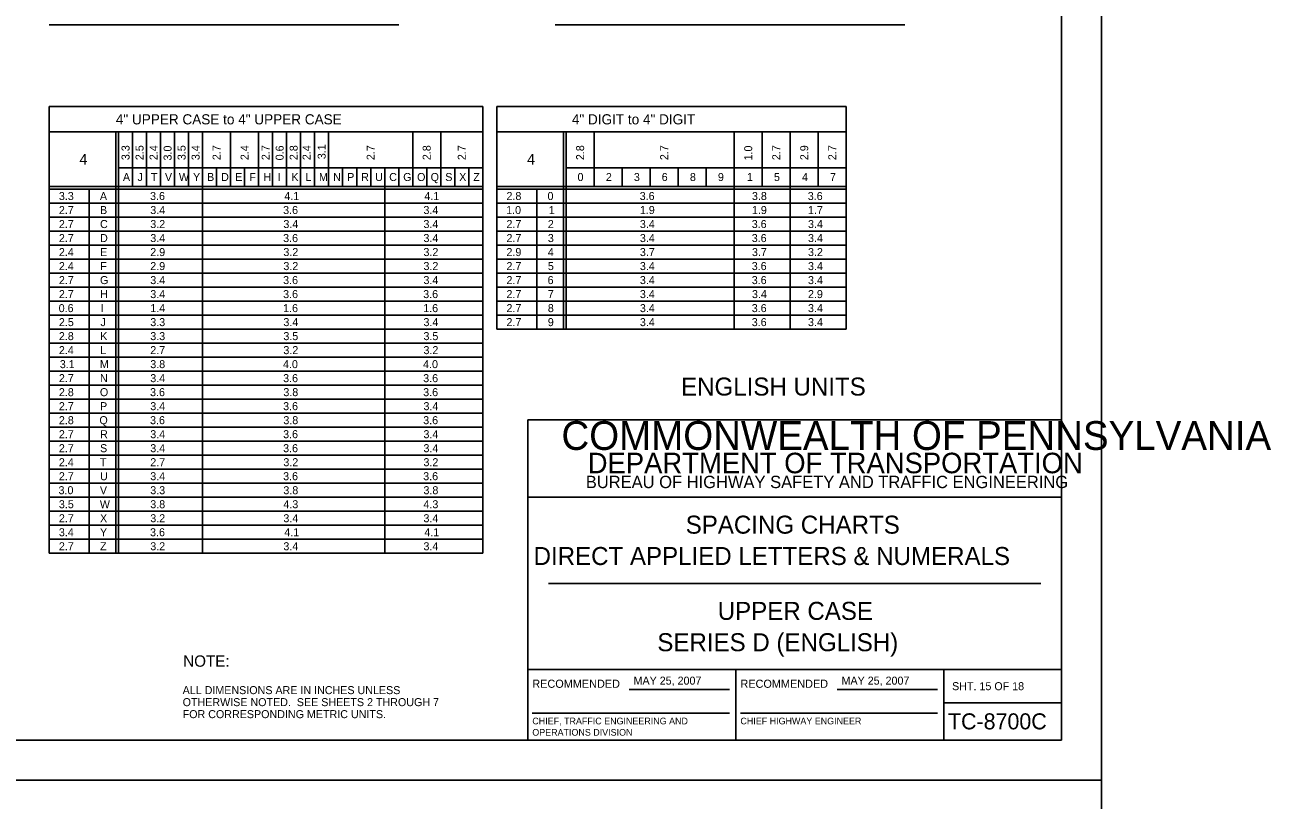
# Model space of a CAD drawing. Extents: x 637580 to 641849, y 297270 to 299646.
# Drawn here: x 640540.8 to 641007.9, y 297856.1 to 298146.6 of the extents above; entities that cross this region are included whole.
import ezdxf

# ---------------------------------------------------------------- set-up
doc = ezdxf.new("R2010")
doc.units = 0
for name, color, linetype in [('1', 7, 'Continuous'), ('2', 7, 'Continuous'), ('XCS-GRID-HVGL', 7, 'Continuous')]:
    doc.layers.add(name, color=color, linetype=linetype)

msp = doc.modelspace()

# ---------------------------------------------------------------- linework, layer by layer
at = {"layer": '1'}
for p, q in [((640929.31, 297878.63), (640929.31, 298442.63)), ((640729.31, 297878.63), (640729.31, 297998.63)), ((640729.31, 297998.63), (640929.31, 297998.63)), ((640929.31, 297969.63), (640729.31, 297969.63)), ((640737.06, 297937.31), (640921.56, 297937.31)), ((640729.31, 297905), (640929.31, 297905)), ((640807.31, 297905), (640807.31, 297878.63)), ((640885.19, 297878.63), (640885.19, 297905)), ((640767.24, 297897.57), (640804.87, 297897.57)), ((640845.24, 297897.57), (640882.87, 297897.57)), ((640730.99, 297888.68), (640804.87, 297888.68)), ((640808.99, 297888.68), (640882.87, 297888.68)), ((640885.19, 297892.63), (640929.31, 297892.63)), ((640929.31, 297878.63), (640143.31, 297878.63)), ((640143.31, 297878.63), (640729.31, 297878.63))]:
    msp.add_line(p, q, dxfattribs=at)
at = {"layer": '2'}
for p, q in [((640549.91, 298146.63), (640680.91, 298146.63)), ((640739.61, 298146.63), (640870.61, 298146.63)), ((640712.41, 298116), (640549.91, 298116)), ((640549.91, 298116), (640549.91, 297948.63)), ((640712.41, 298116), (640712.41, 297948.63)), ((640848.66, 298116), (640717.66, 298116)), ((640717.66, 298116), (640717.66, 298032.63)), ((640848.66, 298032.63), (640848.66, 298116)), ((640549.91, 298106.5), (640712.41, 298106.5)), ((640574.91, 298106.5), (640574.91, 297948.63)), ((640575.91, 298106.5), (640575.91, 297948.63)), ((640581.16, 298106.5), (640581.16, 298086.13)), ((640586.41, 298106.5), (640586.41, 298086.13)), ((640591.66, 298106.5), (640591.66, 298086.13)), ((640596.91, 298106.5), (640596.91, 298086.13)), ((640602.16, 298106.5), (640602.16, 298086.13)), ((640607.41, 298106.5), (640607.41, 297948.63)), ((640617.91, 298106.5), (640617.91, 298086.13)), ((640628.41, 298106.5), (640628.41, 298086.13)), ((640633.66, 298106.5), (640633.66, 298086.13)), ((640638.91, 298106.5), (640638.91, 298086.13)), ((640644.16, 298106.5), (640644.16, 298086.13)), ((640649.41, 298106.5), (640649.41, 298086.13)), ((640654.66, 298106.5), (640654.66, 298086.13)), ((640686.16, 298106.5), (640686.16, 298086.13)), ((640696.66, 298106.5), (640696.66, 298086.13)), ((640717.66, 298106.5), (640848.66, 298106.5)), ((640742.66, 298106.5), (640742.66, 298032.63)), ((640743.66, 298106.5), (640743.66, 298032.63)), ((640754.16, 298106.5), (640754.16, 298086.13)), ((640806.66, 298106.5), (640806.66, 298032.63)), ((640817.16, 298106.5), (640817.16, 298086.13)), ((640827.66, 298106.5), (640827.66, 298032.63)), ((640838.16, 298106.5), (640838.16, 298086.13)), ((640575.91, 298093.13), (640712.41, 298093.13)), ((640612.66, 298093.13), (640612.66, 298086.13)), ((640623.16, 298093.13), (640623.16, 298086.13)), ((640659.91, 298093.13), (640659.91, 298086.13)), ((640665.16, 298093.13), (640665.16, 298086.13)), ((640670.41, 298093.13), (640670.41, 298086.13)), ((640670.41, 298093.13), (640670.41, 298086.13)), ((640675.66, 298093.13), (640675.66, 297948.63)), ((640680.91, 298093.13), (640680.91, 298086.13)), ((640691.41, 298093.13), (640691.41, 298086.13)), ((640701.91, 298093.13), (640701.91, 298086.13)), ((640707.16, 298093.13), (640707.16, 298086.13)), ((640743.66, 298093.13), (640848.66, 298093.13)), ((640764.66, 298093.13), (640764.66, 298086.13)), ((640775.16, 298093.13), (640775.16, 298086.13)), ((640785.66, 298093.13), (640785.66, 298086.13)), ((640796.16, 298093.13), (640796.16, 298086.13)), ((640712.41, 298086.13), (640549.91, 298086.13)), ((640712.41, 298085.13), (640549.91, 298085.13)), ((640564.91, 298085.13), (640564.91, 297948.63)), ((640848.66, 298086.13), (640717.66, 298086.13)), ((640848.66, 298085.13), (640717.66, 298085.13)), ((640732.66, 298085.13), (640732.66, 298032.63)), ((640712.41, 298079.88), (640549.91, 298079.88)), ((640848.66, 298079.88), (640717.66, 298079.88)), ((640712.41, 298074.63), (640549.91, 298074.63)), ((640848.66, 298074.63), (640717.66, 298074.63)), ((640712.41, 298069.38), (640549.91, 298069.38)), ((640848.66, 298069.38), (640717.66, 298069.38)), ((640712.41, 298064.13), (640549.91, 298064.13)), ((640848.66, 298064.13), (640717.66, 298064.13)), ((640712.41, 298058.88), (640549.91, 298058.88)), ((640848.66, 298058.88), (640717.66, 298058.88)), ((640712.41, 298053.63), (640549.91, 298053.63)), ((640848.66, 298053.63), (640717.66, 298053.63)), ((640712.41, 298048.38), (640549.91, 298048.38)), ((640848.66, 298048.38), (640717.66, 298048.38)), ((640712.41, 298043.13), (640549.91, 298043.13)), ((640848.66, 298043.13), (640717.66, 298043.13)), ((640712.41, 298037.88), (640549.91, 298037.88)), ((640848.66, 298037.88), (640717.66, 298037.88)), ((640712.41, 298032.63), (640549.91, 298032.63)), ((640717.66, 298032.63), (640848.66, 298032.63)), ((640712.41, 298027.38), (640549.91, 298027.38)), ((640712.41, 298022.13), (640549.91, 298022.13)), ((640712.41, 298016.88), (640549.91, 298016.88)), ((640712.41, 298011.63), (640549.91, 298011.63)), ((640712.41, 298006.38), (640549.91, 298006.38)), ((640712.41, 298001.13), (640549.91, 298001.13)), ((640712.41, 297995.88), (640549.91, 297995.88)), ((640712.41, 297990.63), (640549.91, 297990.63)), ((640712.41, 297985.38), (640549.91, 297985.38)), ((640712.41, 297980.13), (640549.91, 297980.13)), ((640712.41, 297974.88), (640549.91, 297974.88)), ((640712.41, 297969.63), (640549.91, 297969.63)), ((640712.41, 297964.38), (640549.91, 297964.38)), ((640712.41, 297959.13), (640549.91, 297959.13)), ((640712.41, 297953.88), (640549.91, 297953.88)), ((640549.91, 297948.63), (640549.91, 297948.63)), ((640549.91, 297948.63), (640712.41, 297948.63))]:
    msp.add_line(p, q, dxfattribs=at)
at = {"layer": 'XCS-GRID-HVGL'}
for points in [[(640103.31, 298457.63), (640944.31, 298457.63), (640944.31, 297863.63), (640103.31, 297863.63)], [(640103.31, 297863.63), (640944.31, 297863.63), (640944.31, 297269.63), (640103.31, 297269.63)]]:
    msp.add_lwpolyline(points, close=True, dxfattribs=at)

# ---------------------------------------------------------------- texts
at = {"layer": '1'}
for s, height, p in [('COMMONWEALTH OF PENNSYLVANIA', 10.7828, (640741.9, 297987.36)), ('DEPARTMENT OF TRANSPORTATION', 7.6837, (640751.76, 297978.61)), ('BUREAU OF HIGHWAY SAFETY AND TRAFFIC ENGINEERING', 4.6253, (640751.04, 297973.04)), ('SPACING CHARTS', 6.75, (640788.47, 297955.97)), ('DIRECT APPLIED LETTERS & NUMERALS', 6.75, (640731.47, 297944.22)), ('UPPER CASE', 6.75, (640800.47, 297923.66)), ('SERIES D (ENGLISH)', 6.75, (640777.84, 297911.91)), ('RECOMMENDED', 3.048, (640730.99, 297898.2)), ('RECOMMENDED', 3.048, (640808.99, 297898.2)), ('SHT. 15 OF 18', 3, (640888.32, 297897.31)), ('TC-8700C', 6, (640886.77, 297882.63)), ('CHIEF, TRAFFIC ENGINEERING AND', 2.5, (640730.99, 297884.51)), ('CHIEF HIGHWAY ENGINEER', 2.5, (640808.99, 297884.51)), ('OPERATIONS DIVISION', 2.5, (640730.99, 297880.26))]:
    msp.add_text(s, height=height, dxfattribs=at).set_placement(p)
at = {"layer": '2'}
for s, height, p in [('4" UPPER CASE to 4" UPPER CASE', 3.8, (640574.9, 298109.35)), ('4" DIGIT to 4" DIGIT', 3.8, (640745.81, 298109.35)), ('4', 4, (640561.28, 298094.31)), ('4', 4, (640729.03, 298094.31)), ('A', 3, (640577.56, 298088.13)), ('J', 3, (640583.04, 298088.13)), ('T', 3, (640588.04, 298088.13)), ('V', 3, (640593.31, 298088.13)), ('W', 3, (640598.53, 298088.13)), ('Y', 3, (640603.84, 298088.13)), ('B', 3, (640609.1, 298088.13)), ('D', 3, (640614.35, 298088.13)), ('E', 3, (640619.62, 298088.13)), ('F', 3, (640624.92, 298088.13)), ('H', 3, (640630.19, 298088.13)), ('I', 3, (640635.6, 298088.13)), ('K', 3, (640640.69, 298088.13)), ('L', 3, (640645.94, 298088.13)), ('M', 3, (640651.03, 298088.13)), ('N', 3, (640656.35, 298088.13)), ('P', 3, (640661.6, 298088.13)), ('R', 3, (640666.85, 298088.13)), ('U', 3, (640672.09, 298088.13)), ('C', 3, (640677.35, 298088.13)), ('G', 3, (640682.6, 298088.13)), ('O', 3, (640687.81, 298088.13)), ('Q', 3, (640692.88, 298088.13)), ('S', 3, (640698.37, 298088.13)), ('X', 3, (640703.59, 298088.13)), ('Z', 3, (640708.85, 298088.13)), ('0', 3, (640747.93, 298088.13)), ('2', 3, (640758.56, 298088.13)), ('3', 3, (640769.06, 298088.13)), ('6', 3, (640779.48, 298088.13)), ('8', 3, (640790.06, 298088.13)), ('9', 3, (640800.55, 298088.13)), ('1', 3, (640811.4, 298088.13)), ('5', 3, (640821.56, 298088.13)), ('4', 3, (640832.06, 298088.13)), ('7', 3, (640842.56, 298088.13)), ('3.3', 3, (640553.56, 298081)), ('A', 3, (640568.93, 298081)), ('3.6', 3, (640587.73, 298081)), ('4.1', 3, (640638.03, 298081)), ('4.1', 3, (640690.53, 298081)), ('2.8', 3, (640721.31, 298081)), ('0', 3, (640736.68, 298081)), ('3.6', 3, (640771.23, 298081)), ('3.8', 3, (640813.31, 298081)), ('3.6', 3, (640834.23, 298081)), ('2.7', 3, (640553.56, 298075.75)), ('B', 3, (640568.98, 298075.75)), ('3.4', 3, (640587.81, 298075.75)), ('3.6', 3, (640637.6, 298075.75)), ('3.4', 3, (640690.19, 298075.75)), ('1.0', 3, (640721.18, 298075.75)), ('1', 3, (640737.15, 298075.75)), ('1.9', 3, (640771.3, 298075.75)), ('1.9', 3, (640813.3, 298075.75)), ('1.7', 3, (640834.31, 298075.75)), ('2.7', 3, (640553.56, 298070.5)), ('C', 3, (640568.98, 298070.5)), ('3.2', 3, (640587.81, 298070.5)), ('3.4', 3, (640637.69, 298070.5)), ('3.4', 3, (640690.19, 298070.5)), ('2.7', 3, (640721.31, 298070.5)), ('2', 3, (640736.81, 298070.5)), ('3.4', 3, (640771.31, 298070.5)), ('3.6', 3, (640813.23, 298070.5)), ('3.4', 3, (640834.31, 298070.5)), ('2.7', 3, (640553.56, 298065.25)), ('D', 3, (640568.98, 298065.25)), ('3.4', 3, (640587.81, 298065.25)), ('3.6', 3, (640637.6, 298065.25)), ('3.4', 3, (640690.19, 298065.25)), ('2.7', 3, (640721.31, 298065.25)), ('3', 3, (640736.81, 298065.25)), ('3.4', 3, (640771.31, 298065.25)), ('3.6', 3, (640813.23, 298065.25)), ('3.4', 3, (640834.31, 298065.25)), ('2.4', 3, (640553.56, 298060)), ('E', 3, (640568.99, 298060)), ('2.9', 3, (640587.8, 298060)), ('3.2', 3, (640637.69, 298060)), ('3.2', 3, (640690.19, 298060)), ('2.9', 3, (640721.3, 298060)), ('4', 3, (640736.81, 298060)), ('3.7', 3, (640771.31, 298060)), ('3.7', 3, (640813.31, 298060)), ('3.2', 3, (640834.31, 298060)), ('2.4', 3, (640553.56, 298054.75)), ('F', 3, (640569.05, 298054.75)), ('2.9', 3, (640587.8, 298054.75)), ('3.2', 3, (640637.69, 298054.75)), ('3.2', 3, (640690.19, 298054.75)), ('2.7', 3, (640721.31, 298054.75)), ('5', 3, (640736.81, 298054.75)), ('3.4', 3, (640771.31, 298054.75)), ('3.6', 3, (640813.23, 298054.75)), ('3.4', 3, (640834.31, 298054.75)), ('2.7', 3, (640553.56, 298049.5)), ('G', 3, (640568.98, 298049.5)), ('3.4', 3, (640587.81, 298049.5)), ('3.6', 3, (640637.6, 298049.5)), ('3.4', 3, (640690.19, 298049.5)), ('2.7', 3, (640721.31, 298049.5)), ('6', 3, (640736.73, 298049.5)), ('3.4', 3, (640771.31, 298049.5)), ('3.6', 3, (640813.23, 298049.5)), ('3.4', 3, (640834.31, 298049.5)), ('2.7', 3, (640553.56, 298044.25)), ('H', 3, (640569.06, 298044.25)), ('3.4', 3, (640587.81, 298044.25)), ('3.6', 3, (640637.6, 298044.25)), ('3.6', 3, (640690.1, 298044.25)), ('2.7', 3, (640721.31, 298044.25)), ('7', 3, (640736.81, 298044.25)), ('3.4', 3, (640771.31, 298044.25)), ('3.4', 3, (640813.31, 298044.25)), ('2.9', 3, (640834.3, 298044.25)), ('0.6', 3, (640553.48, 298039)), ('I', 3, (640569.23, 298039)), ('1.4', 3, (640587.81, 298039)), ('1.6', 3, (640637.6, 298039)), ('1.6', 3, (640690.1, 298039)), ('2.7', 3, (640721.31, 298039)), ('8', 3, (640736.81, 298039)), ('3.4', 3, (640771.31, 298039)), ('3.6', 3, (640813.23, 298039)), ('3.4', 3, (640834.31, 298039)), ('2.5', 3, (640553.56, 298033.75)), ('J', 3, (640569.17, 298033.75)), ('3.3', 3, (640587.81, 298033.75)), ('3.4', 3, (640637.69, 298033.75)), ('3.4', 3, (640690.19, 298033.75)), ('2.7', 3, (640721.31, 298033.75)), ('9', 3, (640736.8, 298033.75)), ('3.4', 3, (640771.31, 298033.75)), ('3.6', 3, (640813.23, 298033.75)), ('3.4', 3, (640834.31, 298033.75)), ('2.8', 3, (640553.56, 298028.5)), ('K', 3, (640569.06, 298028.5)), ('3.3', 3, (640587.81, 298028.5)), ('3.5', 3, (640637.69, 298028.5)), ('3.5', 3, (640690.19, 298028.5)), ('2.4', 3, (640553.56, 298023.25)), ('L', 3, (640569.06, 298023.25)), ('2.7', 3, (640587.81, 298023.25)), ('3.2', 3, (640637.69, 298023.25)), ('3.2', 3, (640690.19, 298023.25)), ('3.1', 3, (640553.9, 298018)), ('M', 3, (640568.91, 298018)), ('3.8', 3, (640587.81, 298018)), ('4.0', 3, (640637.56, 298018)), ('4.0', 3, (640690.06, 298018)), ('2.7', 3, (640553.56, 298012.75)), ('N', 3, (640568.98, 298012.75)), ('3.4', 3, (640587.81, 298012.75)), ('3.6', 3, (640637.6, 298012.75)), ('3.6', 3, (640690.1, 298012.75)), ('ENGLISH UNITS', 6.75, (640786.74, 298007.72)), ('2.8', 3, (640553.56, 298007.5)), ('O', 3, (640568.93, 298007.5)), ('3.6', 3, (640587.73, 298007.5)), ('3.8', 3, (640637.69, 298007.5)), ('3.6', 3, (640690.1, 298007.5)), ('2.7', 3, (640553.56, 298002.25)), ('P', 3, (640568.98, 298002.25)), ('3.4', 3, (640587.81, 298002.25)), ('3.6', 3, (640637.6, 298002.25)), ('3.4', 3, (640690.19, 298002.25)), ('2.8', 3, (640553.56, 297997)), ('Q', 3, (640568.75, 297997)), ('3.6', 3, (640587.73, 297997)), ('3.8', 3, (640637.69, 297997)), ('3.6', 3, (640690.1, 297997)), ('2.7', 3, (640553.56, 297991.75)), ('R', 3, (640568.98, 297991.75)), ('3.4', 3, (640587.81, 297991.75)), ('3.6', 3, (640637.6, 297991.75)), ('3.4', 3, (640690.19, 297991.75)), ('2.7', 3, (640553.56, 297986.5)), ('S', 3, (640568.99, 297986.5)), ('3.4', 3, (640587.81, 297986.5)), ('3.6', 3, (640637.6, 297986.5)), ('3.4', 3, (640690.19, 297986.5)), ('2.4', 3, (640553.56, 297981.25)), ('T', 3, (640568.92, 297981.25)), ('2.7', 3, (640587.81, 297981.25)), ('3.2', 3, (640637.69, 297981.25)), ('3.2', 3, (640690.19, 297981.25)), ('2.7', 3, (640553.56, 297976)), ('U', 3, (640568.97, 297976)), ('3.4', 3, (640587.81, 297976)), ('3.6', 3, (640637.6, 297976)), ('3.6', 3, (640690.1, 297976)), ('3.0', 3, (640553.43, 297970.75)), ('V', 3, (640568.93, 297970.75)), ('3.3', 3, (640587.81, 297970.75)), ('3.8', 3, (640637.69, 297970.75)), ('3.8', 3, (640690.19, 297970.75)), ('3.5', 3, (640553.56, 297965.5)), ('W', 3, (640568.91, 297965.5)), ('3.8', 3, (640587.81, 297965.5)), ('4.3', 3, (640637.69, 297965.5)), ('4.3', 3, (640690.19, 297965.5)), ('2.7', 3, (640553.56, 297960.25)), ('X', 3, (640568.97, 297960.25)), ('3.2', 3, (640587.81, 297960.25)), ('3.4', 3, (640637.69, 297960.25)), ('3.4', 3, (640690.19, 297960.25)), ('3.4', 3, (640553.56, 297955)), ('Y', 3, (640568.97, 297955)), ('3.6', 3, (640587.73, 297955)), ('4.1', 3, (640638.03, 297955)), ('4.1', 3, (640690.53, 297955)), ('2.7', 3, (640553.56, 297949.75)), ('Z', 3, (640568.98, 297949.75)), ('3.2', 3, (640587.81, 297949.75)), ('3.4', 3, (640637.69, 297949.75)), ('3.4', 3, (640690.19, 297949.75)), ('NOTE:', 4.25, (640600.16, 297906.1)), ('MAY 25, 2007', 3, (640768.93, 297899.39)), ('ALL DIMENSIONS ARE IN INCHES UNLESS', 3, (640599.94, 297895.83)), ('OTHERWISE NOTED.  SEE SHEETS 2 THROUGH 7', 3, (640599.94, 297891.33)), ('FOR CORRESPONDING METRIC UNITS.', 3, (640599.94, 297886.83))]:
    msp.add_text(s, height=height, dxfattribs=at).set_placement(p)
for s, rotation, p in [('3.3', 90, (640580.04, 298095.96)), ('2.5', 90, (640585.29, 298095.96)), ('2.4', 90, (640590.54, 298095.96)), ('3.0', 90, (640595.79, 298095.83)), ('3.5', 90, (640601.04, 298095.96)), ('3.4', 90, (640606.29, 298095.96)), ('2.7', 90, (640614.16, 298095.96)), ('2.4', 90, (640624.66, 298095.96)), ('2.7', 90, (640632.54, 298095.96)), ('0.6', 90, (640637.79, 298095.88)), ('2.8', 90, (640643.04, 298095.96)), ('2.4', 90, (640647.9, 298095.96)), ('3.1', 90, (640653.54, 298096.31)), ('2.7', 90, (640671.91, 298095.96)), ('2.8', 90, (640692.91, 298095.96)), ('2.7', 90, (640706.04, 298095.96)), ('2.8', 90, (640750.41, 298095.96)), ('2.7', 90, (640781.91, 298095.96)), ('1.0', 90, (640813.41, 298095.83)), ('2.7', 90, (640823.91, 298095.96)), ('2.9', 90, (640834.41, 298095.95)), ('2.7', 90, (640844.91, 298095.96)), ('MAY 25, 2007', 360, (640846.88, 297899.39))]:
    msp.add_text(s, height=3, rotation=rotation, dxfattribs=at).set_placement(p)

doc.saveas('drawing.dxf')
